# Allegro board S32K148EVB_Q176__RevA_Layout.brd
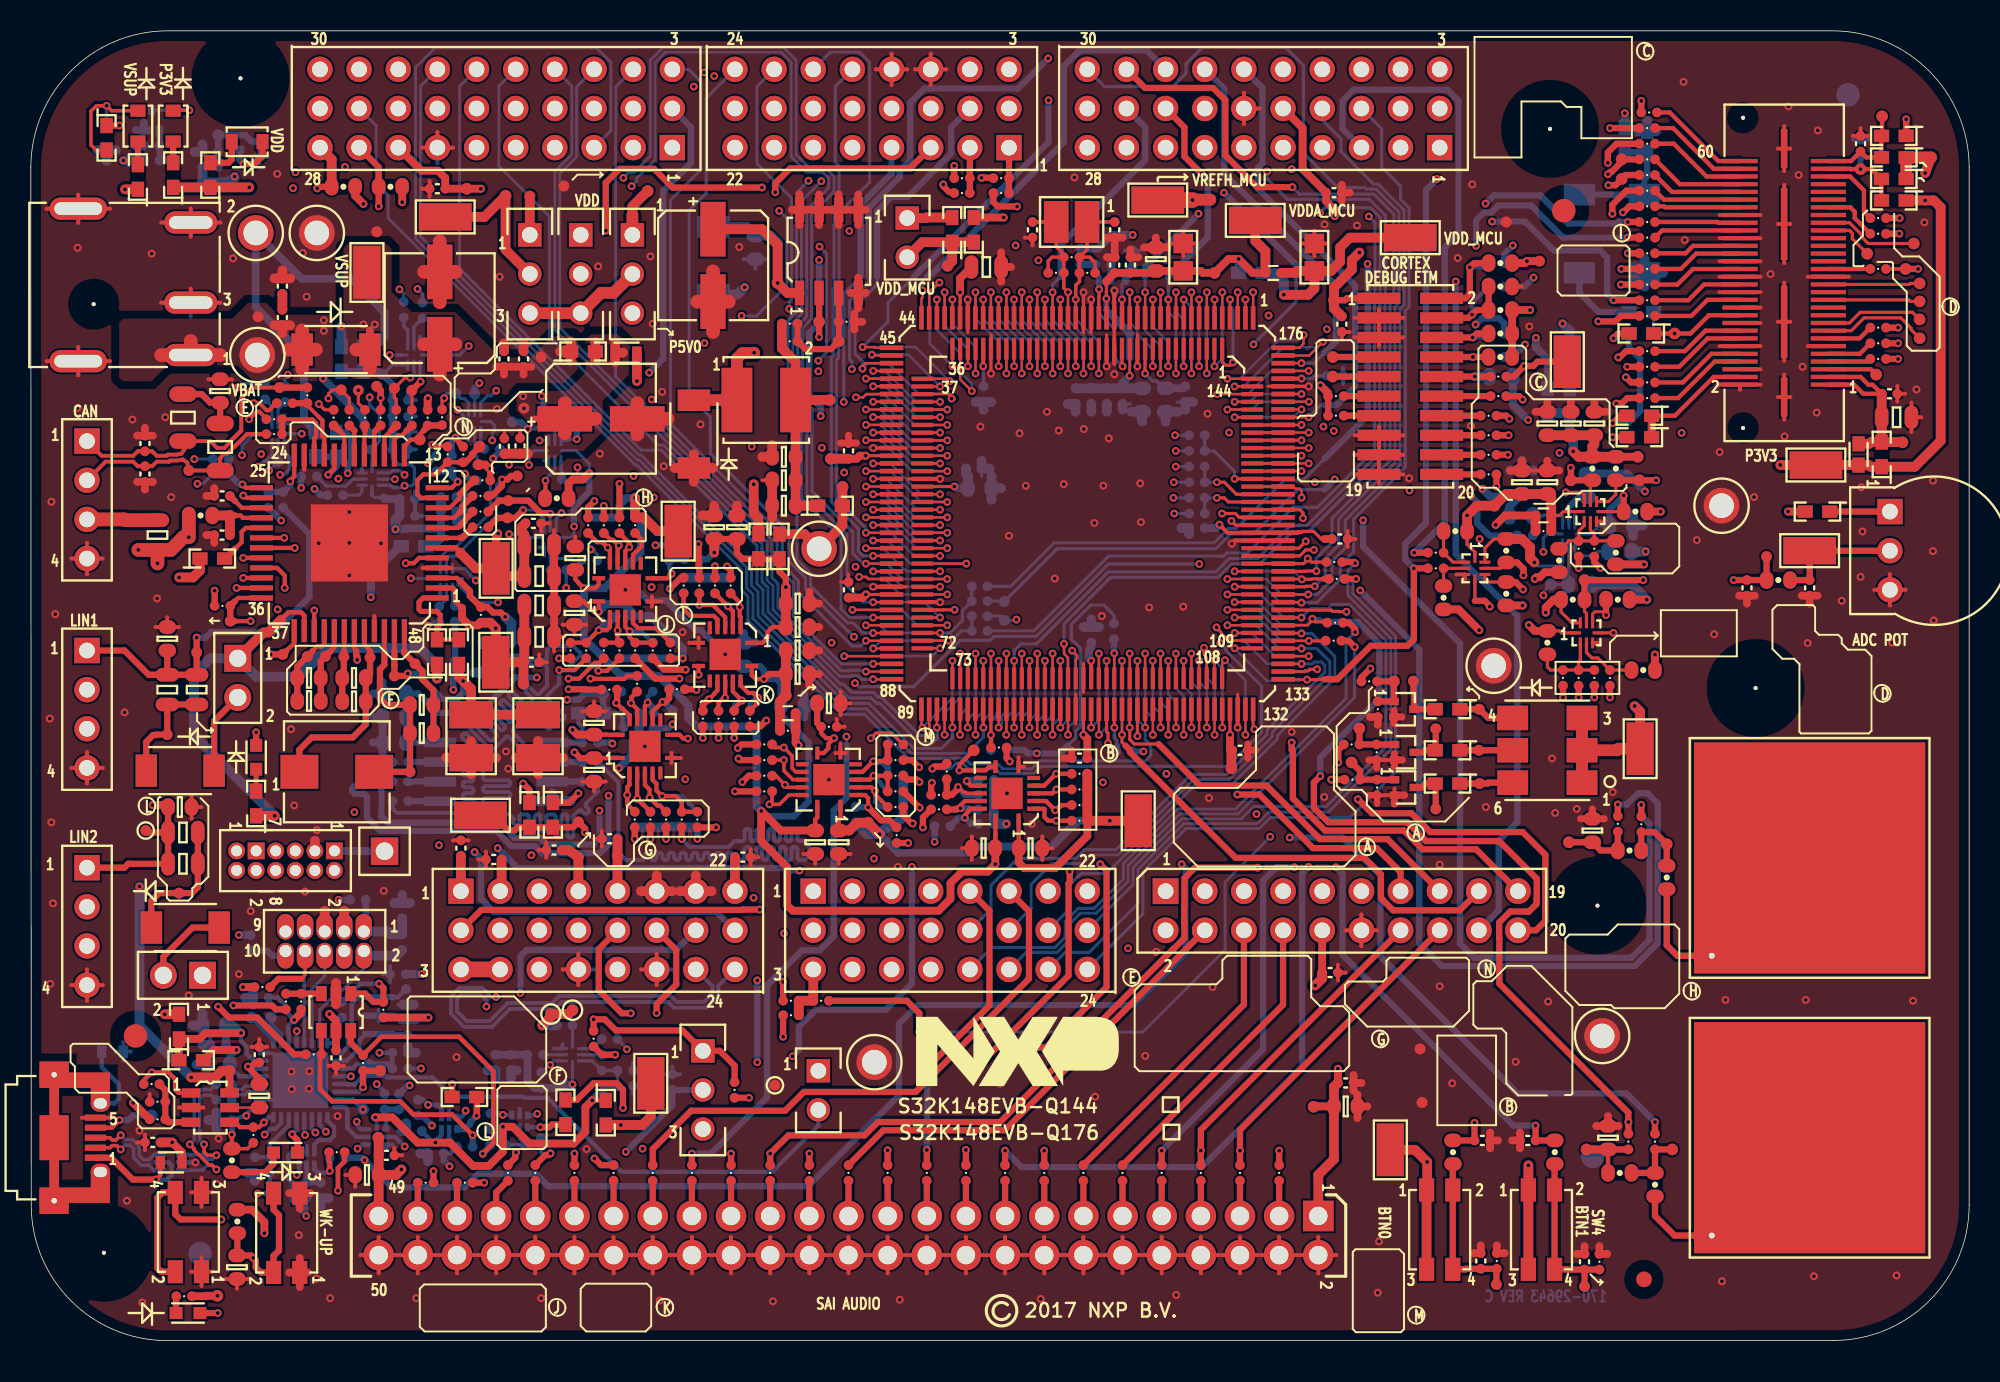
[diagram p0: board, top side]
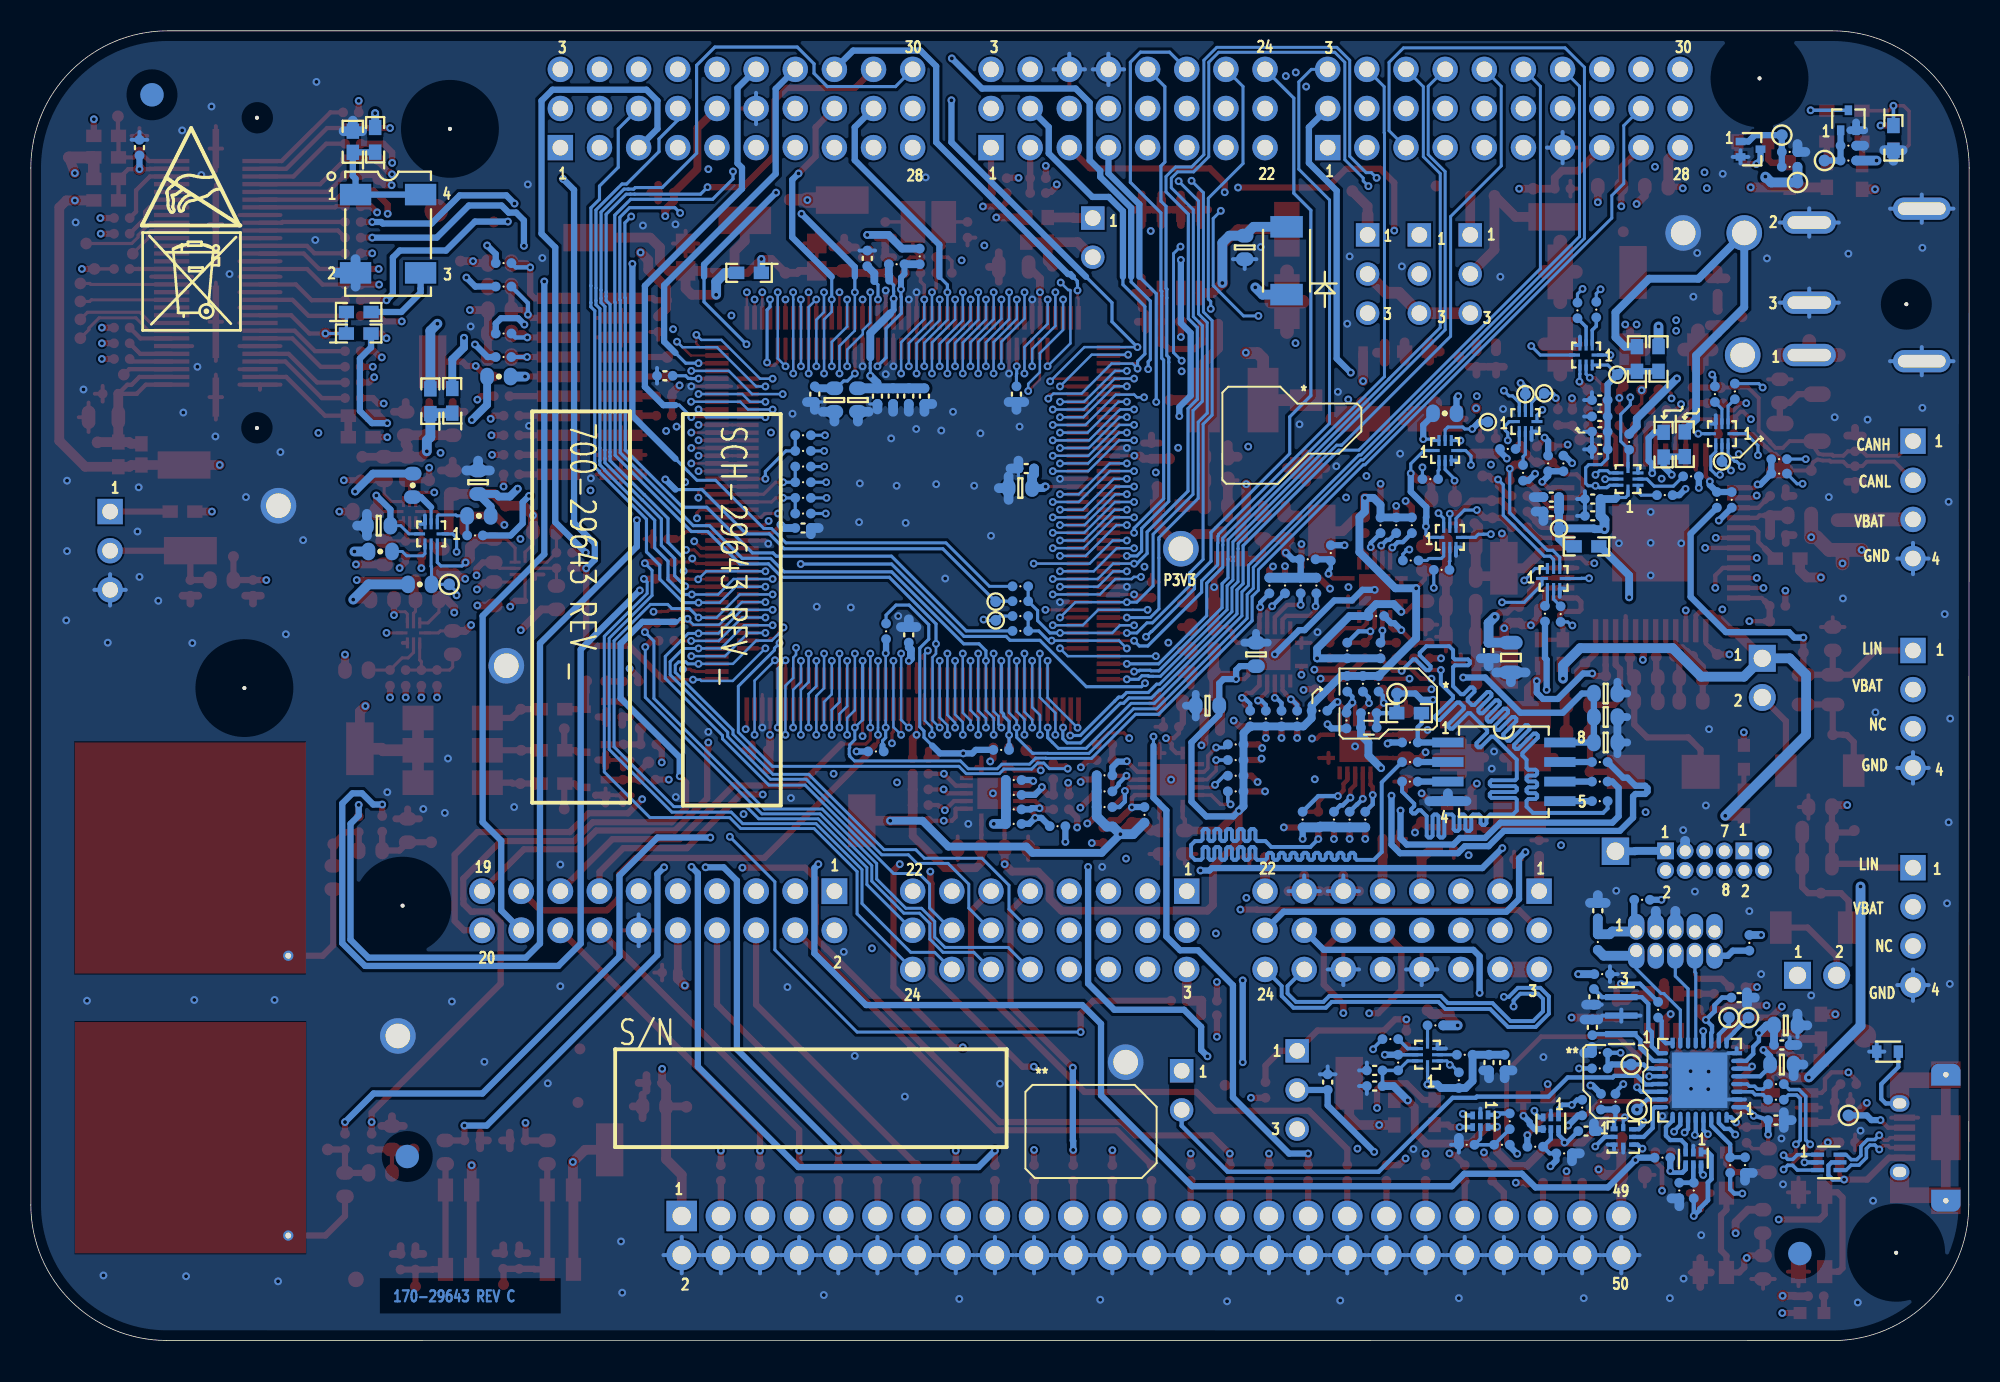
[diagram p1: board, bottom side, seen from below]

Outline 125.76 x 85.01 mm; copper layers: TOP, L2_GND_1, L3_INT_1, L4_PWR_1, L5_PWR_2, L6_INT_2, L7_GND_2, BOTTOM. Coordinates in mm from the lower left corner of the outline.
Outline path: 0,76.12 0.03,8.81 arc(2.6,2.59) 8.83,0 116.94,0.01 arc(123.17,2.59) 125.76,8.81 125.76,76.12 arc(123.15,82.41) 116.87,85.01 8.89,85.01 arc(2.6,82.41) 0,76.12

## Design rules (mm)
net group CLOCK: nets SDA_EXTAL SDA_XTAL
net group DP1: nets N17085305 N17085321
net group DP2: nets CAN_H CAN_L
net group DP3: nets CANH_OUT CANL_OUT
net group DP4: nets SBC_CANH SBC_CANL
net group SDA_USB_CONN_D: nets SDA_USB_CONN_DN SDA_USB_CONN_DP
net group USB_SI_CONN_D: nets SDA_USB_DN SDA_USB_DP
net group MATCH_1: nets ENETSW_INH ENETSW_RESET ENETSW_SCL ENETSW_SDA PTB4/MII_RMII_MDIO PTB5/ENET_MII_RMII_MDC PTB20/FTM6_CH0/ENET_INT PTC0/MII_RMII_RXD1 PTC1/MII_RMII_RXD0 PTC2/MII_RMII_TXD0 PTC17/MII_RMII_RX_DV PTD5/MII_TXD3 PTD6/MII_TXD2 PTD7/MII_RMII_TXD1 PTD8/MII_RXD3 PTD9/MII_RXD2 PTD10/MII_RX_CLK PTD11/MII_RMII_TX_CLK PTD12/MII_RMII_TX_EN
net group MATCH_2: nets PTC2/QSPI_A_IO3 PTC3/QSPI_A_CS PTD7/QSPI_A_IO1 PTD10/QSPI_A_SCK PTD11/QSPI_A_IO0 PTD12/QSPI_A_IO2
net group POW: nets MIC2005_CSLEW POWER_EN SDA_RST SDA_USB_P5V_SENSE VTRG_EN
net group POWER_SPACE: nets P5V0_SDA_USB_CONN_VBUS P5V_SDA_PSW SDA_VOUT33 V_TGTMCU VDD
nets with their own width: min track width 0.254; nets GND

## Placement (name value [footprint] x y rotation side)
C1  0.1uF  [CC0402_25]  26.38 74.76 180 top
C2  0.1uF  [CC0402_25]  84.54 74.51 0 top
C3  12PF  [CC0402_25]  64.99 72.1 270 top
C4  12PF  [CC0402_25]  70.32 72.1 270 top
C5  10uF  [CC0603_OV]  72.99 70.19 90 top
C6  1000pF  [CC0402_25]  70.32 69.81 90 top
C7  1000pF  [CC0402_25]  71.34 69.81 90 top
C8  47uF  [CCE6P8X6P8]  44.26 69.78 270 top
C9  10UF  [CC0805_OV]  61.99 69.68 0 top
C10  0.1uF  [CC0402_25]  16.32 68.44 90 top
C11  47uF  [CCE6P8X6P8]  26.53 67.02 90 top
C12  0.1uF  [CC0402_25]  16.32 66.41 90 top
C13  0.1uF  [CC0402_25]  30.7 63.71 90 top
C14  0.1uF  [CC0402_25]  31.97 63.71 90 top
C15  4700 PF  [CC0603_OV]  12.28 61.63 90 top
C16  47uF  [CCE6P8X6P8]  37 59.83 0 top
C17  1000PF  [CC0603_OV]  98.39 59.52 90 top
C18  0.1UF  [CC0603_OV]  99.91 59.52 90 top
C19  0.1UF  [CC0603_OV]  101.43 59.52 90 top
C20  100PF  [CC0402_25]  7.4 58.23 90 top
C21  0.1uF  [CC0402_25]  31.74 58.07 90 top
C22  0.1uF  [CC0402_25]  30.72 58.05 90 top
C23  1000pF  [CC0402_25]  53.05 57.74 90 top
C24  22uF  [CC0603_OV]  48.86 57.36 180 top
C25  100PF  [CC0402_25]  7.4 56.25 270 top
C26  0.1UF  [CC0603_OV]  48.86 55.84 180 top
C27  0.1UF  [CC0603_OV]  96.74 55.71 90 top
C28  1000PF  [CC0603_OV]  98.39 55.71 90 top
C29  0.01UF  [CC0402_25]  12.41 54.82 180 top
C30  0.1UF  [CC0603_OV]  48.86 54.19 180 top
C31  0.1uF  [CC0402_25]  32.6 53.05 0 top
C32  1000PF  [CC0603_OV]  44.34 52.79 90 top
C41  0.1UF  [CC0603_OV]  45.81 52.79 90 top
C43  0.01UF  [CC0402_25]  12.41 52.28 180 top
C44  1000pF  [CC0402_25]  84.92 52.03 0 top
C45  10UF  [CC0805_OV]  32.98 51.65 0 top
C46  0.1UF  [CC0603_OV]  35.32 50.79 90 top
C47  10UF  [CC0805_OV]  32.98 49.62 0 top
C48  0.1uF  [CC0402_25]  111.34 48.85 270 top
C49  0.1uF  [CC0402_25]  115.4 48.85 270 top
C50  0.1uF  [CC0402_25]  53.05 48.73 90 top
C53  10uF  [CC0603_OV]  49.75 47.84 0 top
C54  10UF  [CC0805_OV]  32.98 47.71 0 top
C55  0.1UF  [CC0603_OV]  35.27 47.23 270 top
C56  0.1UF  [CC0603_OV]  49.75 46.31 0 top
C57  10UF  [CC0805_OV]  32.98 45.68 0 top
C58  220PF  [CC0603_OV]  8.85 45.55 90 top
C59  10uF  [CC0603_OV]  49.75 44.79 0 top
C60  0.1uF  [CC0402_25]  32.47 44.03 0 top
C61  0.1UF  [CC0603_OV]  49.75 43.27 0 top
C62  4700 PF  [CC0603_OV]  18.05 43.01 180 top
C63  4700 PF  [CC0603_OV]  20.97 43.01 180 top
C64  4700 PF  [CC0603_OV]  18.05 41.51 180 top
C65  4700 PF  [CC0603_OV]  20.97 41.49 180 top
C66  10uF  [CC0603_OV]  51.78 41.36 0 top
C67  4700 PF  [CC0603_OV]  25.36 41.26 0 top
C68  0.1UF  [CC0603_OV]  36.54 40.09 90 top
C69  4700 PF  [CC0603_OV]  25.36 39.43 0 top
C70  22uF  [CC1210]  28.56 39.23 270 top
C71  22uF  [CC1210]  32.91 39.23 270 top
C72  0.1uF  [CC0402_25]  78.45 38.31 0 top
C73  1000pF  [CC0402_25]  68.03 37.81 180 top
C75  0.1UF  [CC0603_OV]  36.54 37.04 270 top
C77  220PF  [CC0603_OV]  9.66 34.63 0 top
C78  4.7pF  [CC0603_OV]  101.31 33.11 90 top
C79  0.1uF  [CC0402_25]  37.55 32.57 180 top
C80  0.1UF  [CC0603_OV]  50.89 32.34 270 top
C81  0.1UF  [CC0603_OV]  52.41 32.34 270 top
C82  0.1uF  [CC0402_25]  27.9 31.96 90 top
C83  0.1UF  [CC0603_OV]  61.81 31.96 180 top
C84  0.1UF  [CC0603_OV]  64.86 31.96 0 top
C85  0.1uF  [CC0402_25]  33.95 31.84 180 top
C86  0.1uF  [CC0402_25]  46.19 31.38 0 top
C87  0.1uF  [CC0402_25]  30.04 31.23 180 top
C88  0.1uF  [CC0402_25]  84.29 23.89 0 top
C89  0.1UF  [CC0402_25]  14.82 18.55 90 top
C97  0.1UF  [CC0402_25]  19.8 18.35 270 top
C99  0.1uF  [CC0402_25]  85.31 16.72 0 top
C103  18PF  [CC0603_OV]  14.82 15.89 270 top
C104  10uF  [CC0603_OV]  85.31 15.2 0 top
C108  4.7pF  [CC0603_OV]  102.32 13.17 90 top
C109  0.1uF  [CC0402_25]  94.17 12.99 0 top
C110  0.1uF  [CC0402_25]  97.12 12.99 180 top
C111  10uF  [CC0402_25]  7.91 12.86 180 top
C112  0.1uF  [CC0402_25]  23.08 12.02 0 top
C113  10uF  [CC0603_OV]  21.81 10.75 180 top
C114  0.1uF  [CC0402_25]  94.07 5.17 90 top
C115  0.1uF  [CC0402_25]  100.8 5.12 90 top
C116  4700 PF  [CC0603_OV]  13.37 4.76 270 top
C500  0.1UF  [CC0603]  104.86 77.81 90 bottom
C501  0.1UF  [CC0603_OV]  47 70.95 270 bottom
C502  1000pF  [CC0402_25]  71.49 70.24 90 bottom
C503  0.1uF  [CC0402_25]  84.62 62.62 0 bottom
C504  0.1uF  [CC0402_25]  74.89 61.43 270 bottom
C505  0.1uF  [CC0402_25]  61.81 61.43 270 bottom
C506  0.1uF  [CC0402_25]  70.83 61.3 270 bottom
C507  0.1uF  [CC0402_25]  69.81 61.3 270 bottom
C508  1000pF  [CC0402_25]  68.8 61.3 270 bottom
C509  0.1uF  [CC0402_25]  67.78 61.3 270 bottom
C510  10uF  [CC0603_OV]  73.62 61.05 270 bottom
C511  10uF  [CC0603_OV]  72.1 61.05 270 bottom
C512  0.1uF  [CC0402_25]  23.96 61.05 0 bottom
C513  0.1uF  [CC0402_25]  23.96 59.98 0 bottom
C514  0.1uF  [CC0402_25]  23.96 58.99 0 bottom
C515  0.1uF  [CC0402_25]  23.96 57.85 0 bottom
C516  1000pF  [CC0402_25]  61.18 56.6 0 bottom
C517  0.1UF  [CC0603_OV]  96.74 55.71 90 bottom
C518  10uF  [CC0603_OV]  61.56 55.33 0 bottom
C519  0.1uF  [CC0402_25]  27.11 54.75 0 bottom
C520  0.1uF  [CC0402_25]  24.42 54.62 0 bottom
C521  0.1uF  [CC0402_25]  27.11 53.81 0 bottom
C522  0.1uF  [CC0402_25]  24.42 53.53 0 bottom
C523  0.1UF  [CC0603_OV]  103.19 52.89 0 bottom
C524  1000pF  [CC0402_25]  75.65 52.74 180 bottom
C525  0.1uF  [CC0402_25]  68.8 45.81 90 bottom
C526  0.1uF  [CC0402_25]  31.18 44.79 270 bottom
C527  0.1UF  [CC0603_OV]  46.27 44.54 90 bottom
C528  10UF  [CC0805_OV]  29.73 44.33 270 bottom
C529  1000PF  [CC0603_OV]  23.58 42 180 bottom
C530  1000PF  [CC0603_OV]  49.42 41.21 0 bottom
C531  0.1UF  [CC0603_OV]  23.58 40.47 180 bottom
C532  10uF  [CC0603_OV]  23.58 38.82 180 bottom
C533  0.1UF  [CC0402_25]  24.09 27.9 90 bottom
C534  22PF  [CC0402_25]  24.35 22.31 270 bottom
C535  4.7uF  [CC0402_25]  14.92 22.26 180 bottom
C536  10uF  [CC0603_OV]  11.9 20.46 180 bottom
C537  22PF  [CC0402_25]  24.45 20.33 90 bottom
C538  0.1UF  [CC0402_25]  12.15 19.19 180 bottom
C539  4.7uF  [CC0402_25]  31.15 18.04 270 bottom
C540  0.1UF  [CC0402_25]  30.14 18.04 270 bottom
C541  2.2UF  [CC0603_OV]  12.15 17.92 180 bottom
C542  4.7uF  [CC0402_25]  38.57 17.54 0 bottom
C543  1000pF  [CC0402_25]  41.62 16.77 90 bottom
C544  0.1UF  [CC0402_25]  38.57 16.52 0 bottom
C545  1.0UF  [CC0402_25]  12.53 14.31 180 bottom
C546  4.7uF  [CC0402_25]  24.85 13.6 180 bottom
C547  0.1uF  [CC0402_25]  118.71 77.43 90 bottom
C548  0.1uF  [CC0402_25]  118.71 77.68 90 top
C549  0.1uF  [CC0402_25]  120.59 61.45 0 top
C550  10UF  [CC0805_OV]  121.04 59.93 0 top
C551  0.1uF  [CC0402_25]  85.05 65.97 270 top
D1  VC080505C150RP  [0805]  74.76 70.32 90 top
D2  VC080505C150RP  [0805]  83.27 70.32 90 top
D4  PMEG3050EP  [SOD-128]  19.8 64.32 0 top
D5  PMEG6045ETP  [SOD-128]  43.01 58.84 90 top
D6  LED RED/GRN/BL  [LED6_5X6MM]  98.39 38.31 180 top
D7  LY L29K-H1K2-26-Z  [LED_0603]  14.62 37.86 90 top
D8  PMEG3050EP  [SOD-128]  9.69 36.99 180 top
D9  PMEG3050EP  [SOD-128]  10.02 26.81 180 top
D10  LED GREEN  [LED_0603]  16.52 12.2 0 top
D11  RED  [LED_0603]  10.2 1.79 0 top
D500  PMEG6045ETP  [SOD-128]  44.28 70.09 90 bottom
DS1  ORANGE  [LED2_2P1X1P5_NSP]  6.95 78.83 270 top
DS2  ORANGE  [LED2_2P1X1P5_NSP]  9.23 78.83 270 top
DS3  ORANGE  [LED2_2P1X1P5_NSP]  14.03 77.81 180 top
GND1  5006  [TP_TH_063]  18.55 71.89 0 top
GND2  5006  [TP_TH_063]  109.69 54.19 0 top
GND3  5006  [TP_TH_063]  94.91 43.8 270 top
GND4  5006  [TP_TH_063]  101.94 19.77 0 top
GND5  5006  [TP_TH_063]  54.72 18.07 0 top
J1  ESQ-108-33-T-T  [CON_3X8_100_TH]  63.46 77.43 180 top
J2  ESQ-110-33-T-T  [CON_3X10_100_TH]  41.62 77.43 180 top
J3  ESQ-108-33-T-T  [CON_3X8_100_TH]  27.9 29.17 0 top
J4  ESQ-108-33-T-T  [CON_3X8_100_TH]  50.76 29.17 0 top
J5  CON 2X10  [HDR210_ESQ_SKT]  73.62 29.17 90 top
J6  ESQ-110-33-T-T  [CON_3X10_100_TH]  91.4 77.43 180 top
J7  HDR TH 1X3  [HDR103]  35.67 71.77 0 top
J8  HDR TH 1X3  [HDR103]  39.03 71.77 0 top
J9  CON PWR 3  [CON3_PWR_JACK_TH_PJ051A]  10.38 63.97 0 top
J10  HDR_2X10  [HDR210_FTSH_SM]  89.5 61.94 0 top
J11  HDR 1X4 RA  [CON_HDR_4M_100_TH_RA]  3.64 58.38 270 top
J12  HDR1X2  [HDR1X2_5P48X2P69]  13.42 44.28 270 top
J13  HDR 1X4 RA  [CON_HDR_4M_100_TH_RA]  3.64 44.79 270 top
J14  HDR_2X2  [HDR2X2_50MIL]  14.62 31.79 270 top
J15  HDR_2X4  [HDR2X4_50MIL]  19.7 31.79 270 top
J16  QSH-030-01-L-D-A-K-TR  [CON_60S_QSH_SM_A]  113.75 69.3 90 top
J17  HDR 1X4 RA  [CON_HDR_4M_100_TH_RA]  3.64 30.69 270 top
J18  HDR TH 1X3  [HDR103]  32.37 71.77 0 top
J19  HDR_1X2  [HDR102]  56.86 72.86 0 top
J20  HDR 2X5  [CON_2RH_10_50]  21.6 26.55 180 top
J21  HDR1X2  [HDR1X2_5P48X2P69]  11.14 23.71 180 top
J22  HDR TH 1X3  [HDR103]  43.6 18.81 0 top
J23  HDR 1X2 TH  [SH_HDR102_BOTTOM]  51.09 17.51 0 top
J24  USB_MICRO_AB  [CON_MICROAB_10F_25_SM_RA]  1.61 13.17 0 top
JP1  HDR 1X1  [HDR101_045T]  22.95 31.76 0 top
L1  30 OHM  [IND_0402]  80.61 69.3 180 top
L2  330 OHM  [IND_1608]  38.62 64.12 180 top
L3  4.7uH  [IND_5P2X5P2]  47.71 61.05 0 top
L4  120OHM  [IND_0603]  118.58 57.52 90 top
L6  30 OHM  [IND_0402]  98.13 53.55 0 top
L7  30 OHM  [IND_0402]  49.11 40.73 180 top
L8  22uH  [IND2_6P5X6P2MM_SM]  19.85 36.92 0 top
L9  330 OHM  [IND_1608]  9.11 11.57 0 top
L500  30 OHM  [IND_0402]  38.95 39.79 0 bottom
L501  330 OHM  [IND_1608]  5.3 18.76 0 bottom
NOREF  -  []  28.79 59 0 top
NOREF#2  -  []  50.76 24.09 0 top
NOREF#3  -  []  41.56 37.82 90 top
NOREF#4  -  []  17.56 45.75 90 top
NOREF#5  -  []  8.89 85.01 0 top
NOREF#6  -  []  26.25 22.82 0 top
NOREF#7  -  []  45.68 26.63 90 top
NOREF#8  -  []  11.07 4.47 90 top
NOREF#9  -  []  2.13 81.89 0 top
NOREF#10  -  []  7.49 36.99 0 top
NOREF#11  -  []  24.45 64.62 0 top
NOREF#12  -  [unnamed#2]  99.45 73.34 0 top
NOREF#13  -  []  26.2 34.16 0 top
NOREF#14  -  []  34.49 18.15 90 top
NOREF#15  -  []  68.54 82.51 0 top
NOREF#16  -  []  34.42 51.51 0 top
NOREF#17  -  []  33.29 51.48 90 top
NOREF#18  -  []  62.83 16.01 0 top
NOREF#19  -  []  64.41 35.19 0 top
NOREF#20  -  []  96.49 43.8 0 top
NOREF#21  -  []  56.31 18.07 0 top
NOREF#22  -  []  39.57 47 90 top
NOREF#23  -  []  125.76 8.81 90 top
NOREF#24  -  []  65.11 83.78 0 top
NOREF#25  -  [unnamed#2]  101.64 28.23 0 top
NOREF#26  -  []  93.69 49.37 90 top
NOREF#27  -  []  42.93 70.79 0 top
NOREF#28  -  []  52.73 51.39 0 top
NOREF#29  -  []  93.04 50.12 90 top
NOREF#30  -  [unnamed#2]  4.74 5.7 0 top
NOREF#31  -  []  26.96 48.81 0 top
NOREF#32  -  []  104.61 4.8 90 top
NOREF#33  -  []  101.38 53.19 90 top
NOREF#34  -  []  103.21 25.36 90 top
NOREF#35  -  []  0 76.12 0 top
NOREF#36  -  []  61.61 36.52 0 top
NOREF#37  -  []  105.5 4.38 0 top
NOREF#38  -  []  18.09 25.05 90 top
NOREF#39  -  []  103.53 19.77 0 top
NOREF#40  -  [unnamed#2]  111.9 42.35 0 top
NOREF#41  -  []  100.53 45.28 0 top
NOREF#42  -  []  36.84 47.98 0 top
NOREF#43  -  []  42.93 68.09 90 top
NOREF#44  -  []  15.64 59.51 0 top
NOREF#45  -  []  98.13 25.36 0 top
NOREF#46  -  []  21.49 33.12 0 top
NOREF#47  -  []  59.79 42.98 90 top
NOREF#48  -  []  116.94 0.01 90 top
NOREF#49  -  []  24.41 30.4 90 top
NOREF#50  -  []  50.31 58.45 90 top
NOREF#51  -  []  12.02 28.16 90 top
NOREF#52  -  []  100.2 45.31 0 top
NOREF#53  -  []  28.99 59.03 90 top
NOREF#54  -  []  130.47 -13.91 0 top
NOREF#55  -  []  34.2 57.15 90 top
NOREF#56  -  []  17.8 62.97 90 top
NOREF#57  -  []  19.85 0 90 top
NOREF#58  -  []  88.86 82.51 0 top
NOREF#59  -  []  34 57.12 0 top
NOREF#60  -  []  26.56 35.01 90 top
NOREF#61  -  []  26.56 35.01 0 top
NOREF#62  -  []  51.49 34.39 0 top
NOREF#63  -  []  93.06 50.85 0 top
NOREF#64  -  []  70.19 22.82 90 top
NOREF#65  -  []  7.82 26.81 0 top
NOREF#66  -  []  -98.69 -309.48 0 top
NOREF#67  -  []  52.85 36.08 0 top
NOREF#68  -  []  84 69.21 0 top
NOREF#69  -  []  37.57 47 0 top
NOREF#70  -  []  12.02 30.86 0 top
NOREF#71  -  []  38.84 36.84 0 top
NOREF#72  -  []  73.62 29.17 0 top
NOREF#73  -  [unnamed#2]  6.79 19.77 0 top
NOREF#74  -  []  69.43 83.78 90 top
NOREF#75  -  []  40.39 46.9 90 top
NOREF#76  -  []  100.11 -20.92 0 top
NOREF#77  -  []  65.06 34.52 90 top
NOREF#78  -  []  8.42 13.05 0 top
NOREF#79  -  []  198.26 -169.31 0 top
NOREF#80  -  []  22.57 5.55 0 top
NOREF#81  -  []  33.69 51.48 0 top
NOREF#82  -  []  16.79 58.86 90 top
NOREF#83  -  []  135.92 59.61 0 top
NOREF#84  -  []  26.2 34.16 0 top
NOREF#85  -  []  90.55 9.77 0 top
NOREF#86  -  []  12.08 45.75 0 top
NOREF#87  -  []  17.8 65.67 0 top
NOREF#88  -  [unnamed#2]  104.66 3.97 0 top
NOREF#89  -  []  68.54 26.63 90 top
NOREF#90  -  []  16.18 71.89 0 top
NOREF#91  -  []  35.34 17.93 90 top
NOREF#92  -  []  26.56 35.01 90 top
NOREF#93  -  []  111.28 54.19 0 top
NOREF#94  -  []  75.49 69.21 0 top
NOREF#95  -  []  100.46 53.18 0 top
NOREF#96  -  []  99.38 53.01 0 top
NOREF#97  -  []  43.27 83.78 0 top
NOREF#98  -  []  33.6 57.12 90 top
NOREF#99  -  []  6.95 77.83 90 top
NOREF#100  -  []  44.36 59.54 0 top
NOREF#101  -  []  68.06 34.44 90 top
NOREF#102  -  []  9.37 4.47 0 top
NOREF#103  -  []  78.85 67.87 0 top
NOREF#104  -  []  34.72 57.14 0 top
NOREF#105  -  []  21.49 56.32 90 top
NOREF#106  -  []  11.69 38.34 90 top
NOREF#107  -  []  22.34 55.3 90 top
NOREF#108  -  []  93.89 49.5 90 top
NOREF#109  -  []  101.58 53.16 90 top
NOREF#110  -  []  106.04 41.36 90 top
NOREF#111  -  []  45.81 61.05 0 top
NOREF#112  -  []  24.19 27.37 90 top
NOREF#113  -  []  31.65 34.17 90 top
NOREF#114  -  []  33.89 51.51 90 top
NOREF#115  -  []  53.34 65.6 0 top
NOREF#116  -  []  43.01 56.64 90 top
NOREF#117  -  []  25.05 63.35 90 top
NOREF#118  -  []  97.16 4.62 90 top
NOREF#119  -  [unnamed#2]  98.56 78.65 0 top
NOREF#120  -  []  40.29 47.98 90 top
NOREF#121  -  []  101.13 45.31 90 top
NOREF#122  -  []  96.14 36.21 90 top
NOREF#123  -  []  50.05 37.41 0 top
NOREF#124  -  []  73.62 29.17 0 top
NOREF#125  -  []  8.66 -38.53 0 top
NOREF#126  -  []  51.03 38.13 0 top
NOREF#127  -  []  13.03 77.81 0 top
NOREF#128  -  []  0.02 12.13 0 top
NOREF#129  -  []  68.54 77.43 90 top
NOREF#130  -  []  45.11 58.45 0 top
NOREF#131  -  []  97.16 9.77 0 top
NOREF#132  -  []  86.21 69.21 90 top
NOREF#133  -  []  45.37 47.11 0 top
NOREF#134  -  []  99.98 51.74 90 top
NOREF#135  -  []  16.24 58.24 90 top
NOREF#136  -  []  95.76 63.06 270 top
NOREF#137  -  []  17.6 64.32 0 top
NOREF#138  -  []  8.6 23.71 0 top
NOREF#139  -  []  -408 -310.75 0 top
NOREF#140  -  []  44.28 67.89 90 top
NOREF#141  -  []  38.11 37.82 0 top
NOREF#142  -  []  18.76 82.51 0 top
NOREF#143  -  []  93.2 8.4 0 top
NOREF#144  -  []  15.51 29.91 0 top
NOREF#145  -  []  99.81 8.4 0 top
NOREF#146  -  []  -30.62 -120.06 0 top
NOREF#147  -  []  17.45 4.42 90 top
NOREF#148  -  []  45.55 46.26 0 top
NOREF#149  -  []  43.32 45.29 0 top
NOREF#150  -  []  52.53 34.68 90 top
NOREF#151  -  []  28.39 59 90 top
NOREF#152  -  []  86.19 83.78 90 top
NOREF#153  -  []  31.65 34.17 90 top
NOREF#154  -  []  27.16 48.84 90 top
NOREF#155  -  []  64.08 33.79 90 top
NOREF#156  -  []  45.68 77.43 90 top
NOREF#157  -  []  130.77 36.28 0 top
NOREF#158  -  []  13.35 31.79 0 top
NOREF#159  -  []  44.36 56.84 90 top
NOREF#160  -  []  119.21 83.78 90 top
NOREF#161  -  []  14.8 13 0 top
NOREF#162  -  []  26.56 35.01 0 top
NOREF#163  -  []  57.84 57.93 90 top
NOREF#164  -  []  18.76 77.43 90 top
NOREF#165  -  []  21.49 55.52 90 top
NOREF#166  -  []  49.02 46.36 90 top
NOREF#167  -  []  58.54 63.68 0 top
NOREF#168  -  []  15.75 4.42 0 top
NOREF#169  -  []  20.59 27.37 0 top
NOREF#170  -  []  99.06 52.98 0 top
NOREF#171  -  []  78.54 63.68 90 top
NOREF#172  -  []  38.01 37.49 0 top
NOREF#173  -  []  -381.97 214.4 0 top
NOREF#174  -  []  25.6 63.97 90 top
NOREF#175  -  []  13.22 9.45 90 top
NOREF#176  -  []  101.33 45.28 90 top
NOREF#177  -  []  57.84 62.43 0 top
NOREF#178  -  []  11.69 41.04 0 top
NOREF#179  -  []  62.58 37.24 0 top
NOREF#180  -  []  40.84 36.84 90 top
NOREF#181  -  []  13.42 41.74 90 top
NOREF#182  -  []  27.9 24.09 0 top
NOREF#183  -  []  39.08 82.51 0 top
NOREF#184  -  []  20.14 71.89 0 top
NOREF#185  -  []  77.7 69.21 90 top
NOREF#186  -  []  27.9 24.09 0 top
NOREF#187  -  []  16.28 63.97 0 top
NOREF#188  -  []  24.13 64.59 0 top
NOREF#189  -  []  83.27 69.43 90 top
NOREF#190  -  []  100.78 53.16 0 top
NOREF#191  -  []  47.33 22.82 90 top
NOREF#192  -  []  93.05 83.78 0 top
NOREF#193  -  []  60.59 1.94 0 top
NOREF#194  -  []  29.52 59.02 0 top
NOREF#195  -  []  180.28 85.26 0 top
NOREF#196  -  []  60.92 82.51 0 top
NOREF#197  -  []  45.68 82.51 0 top
NOREF#198  -  []  56.5 35.33 90 top
NOREF#199  -  []  18.43 31.79 0 top
NOREF#200  -  []  34.49 18.95 90 top
NOREF#201  -  []  26.56 35.01 90 top
NOREF#202  -  []  53.5 35.41 90 top
NOREF#203  -  []  26.56 35.01 90 top
NOREF#204  -  []  27.69 48.84 0 top
NOREF#205  -  []  15.32 59.49 0 top
NOREF#206  -  []  74.76 69.43 90 top
NOREF#207  -  []  96.14 40.41 0 top
NOREF#208  -  []  34.52 17.83 0 top
NOREF#209  -  []  26.56 48.81 90 top
NOREF#210  -  [unnamed#2]  13.6 81.93 0 top
NOREF#211  -  []  36.74 47.65 0 top
NOREF#212  -  []  12.61 25.05 0 top
NOREF#213  -  []  50.76 24.09 0 top
NOREF#214  -  []  19.6 9.4 90 top
NOREF#215  -  []  43.32 43.79 90 top
NOREF#216  -  []  21.51 55.19 0 top
NOREF#217  -  []  100.94 41.36 0 top
NOREF#218  -  []  49.11 22.82 0 top
NOREF#219  -  []  44.05 42.81 90 top
NOREF#220  -  []  41.66 36.74 90 top
NOREF#221  -  []  19.11 29.91 90 top
NOREF#222  -  []  9.23 77.83 90 top
NOREF#223  -  []  96.48 26.63 90 top
NOREF#224  -  []  90.55 4.62 90 top
NOREF#225  -  []  98 4.8 90 top
NOREF#226  -  []  100.53 52.36 90 top
NOREF#227  -  []  91.82 68.65 180 bottom
NOREF#228  -  []  154.27 61.05 270 bottom
NOREF#229  -  []  150.33 76.79 180 bottom
NOREF#230  -  []  54.61 34.64 180 bottom
NOREF#231  -  []  165.32 74.38 270 bottom
NOREF#232  -  [unnamed#2]  10.99 5.65 180 bottom
NOREF#233  -  [unnamed#2]  117.89 80.86 180 bottom
NOREF#234  -  []  153.89 64.35 180 bottom
NOREF#235  -  []  54.66 42.01 180 bottom
NOREF#236  -  [unnamed#2]  101.33 11.95 180 bottom
NOREF#237  -  []  121.45 63.79 180 bottom
NOREF#238  -  []  177.63 32.34 180 bottom
P1  TSW-125-07-F-D  [HDR225]  83.53 8.09 270 top
Q1  MMBT3904TT1G  [SC_75]  89.09 40.98 270 top
Q2  MMBT3904TT1G  [SC_75]  89.12 38.19 270 top
Q3  MMBT3904TT1G  [SC_75]  89.12 35.9 270 top
Q500  MMBT3904TT1G  [SC_75]  7.84 79.21 180 bottom
Q501  MMBT3904TT1G  [SC_75]  14.19 77.33 270 bottom
R1  33 OHM  [RC0402_25]  104.99 79.72 180 top
R2  33  [RC0402_25]  104.86 78.7 180 top
R3  0  [RC0603]  120.87 78.19 180 top
R4  0  [RC0603]  4.91 78.06 270 top
R5  33 OHM  [RC0402_25]  104.86 77.68 180 top
R6  0  [RC0603]  120.87 76.79 180 top
R7  33 OHM  [RC0402_25]  104.86 76.67 180 top
R8  33 OHM  [RC0402_25]  104.86 75.65 180 top
R9  560  [RC0603]  9.23 75.65 90 top
R12  560  [RC0603]  11.65 75.65 90 top
R13  1.8K  [RC0603]  6.95 75.52 90 top
R14  0  [RC0402_25]  60.41 75.45 0 top
R34  0  [RC0402_25]  62.95 75.45 0 top
R35  0  [RC0603]  120.87 75.4 180 top
R36  10K  [RC0603_OV]  20.28 74.89 180 top
R37  10K  [RC0603_OV]  23.33 74.89 180 top
R38  33 OHM  [RC0402_25]  104.86 74.64 180 top
R39  0  [RC0402_25]  60.41 74.48 0 top
R40  0  [RC0402_25]  62.95 74.48 0 top
R41  0  [RC0603]  120.87 74 180 top
R46  33 OHM  [RC0402_25]  104.86 73.62 180 top
R55  0  [RC0402_25]  119.85 72.86 180 top
R58  33 OHM  [RC0402_25]  104.86 72.6 180 top
R59  0  [RC0603]  59.78 72.1 90 top
R60  0  [RC0603]  61.18 72.1 90 top
R61  0  [RC0402_25]  119.85 71.84 180 top
R62  33 OHM  [RC0402_25]  104.86 71.59 180 top
R63  33 OHM  [RC0402_25]  104.86 70.57 180 top
R64  0  [RC0402_25]  67.53 70.32 180 top
R72  10K  [RC0603_OV]  95.34 69.94 180 top
R74  33 OHM  [RC0402_25]  104.86 69.56 180 top
R75  0  [RC0402_25]  119.85 69.56 180 top
R76  0  [RC0402_25]  66.51 69.3 0 top
R78  0  [RC0402_25]  68.54 69.3 180 top
R79  33 OHM  [RC0402_25]  104.86 68.54 180 top
R80  10K  [RC0603_OV]  95.34 68.41 0 top
R81  33 OHM  [RC0402_25]  104.86 67.52 180 top
R90  10K  [RC0603_OV]  95.34 66.89 180 top
R91  33 OHM  [RC0402_25]  104.86 66.51 180 top
R92  1.0K  [RC0402_25]  52.92 66.13 0 top
R93  3.09K  [RC0402_25]  49.24 66 0 top
R94  0  [RC0402_25]  119.85 65.75 180 top
R95  10K  [RC0603_OV]  95.34 65.36 180 top
R96  0  [RC0603]  104.48 65.36 180 top
R97  1.69K  [RC0402_25]  49.24 64.86 0 top
R98  0  [RC0402_25]  119.85 64.73 180 top
R102  33 OHM  [RC0402_25]  104.86 64.22 180 top
R106  0  [RC0603]  35.83 64.2 0 top
R107  10K  [RC0603_OV]  95.34 63.84 180 top
R108  0  [RC0402_25]  119.85 63.71 180 top
R109  33 OHM  [RC0402_25]  104.86 63.21 180 top
R110  0  [RC0402_25]  95.21 62.57 0 top
R111  33 OHM  [RC0402_25]  104.86 62.19 180 top
R112  0  [RC0402_25]  17.95 61.35 90 top
R113  0  [RC0402_25]  84.67 61.3 0 top
R114  0  [RC0402_25]  95.21 61.3 0 top
R115  33 OHM  [RC0402_25]  104.86 61.17 180 top
R119  0  [RC0402_25]  16.47 60.84 180 top
R121  0  [RC0402_25]  84.67 60.03 0 top
R122  0  [RC0402_25]  94.58 60.03 0 top
R123  0  [RC0603]  104.36 60.03 180 top
R124  0  [RC0402_25]  26.68 59.93 90 top
R125  60.4  [RC1206_OV]  9.87 59.9 90 top
R126  0  [RC0402_25]  19.65 59.9 270 top
R127  0  [RC0402_25]  20.66 59.9 270 top
R128  0  [RC0402_25]  21.68 59.9 270 top
R129  0  [RC0402_25]  22.69 59.9 270 top
R130  0  [RC0402_25]  23.71 59.9 270 top
R131  0  [RC0402_25]  24.73 59.9 270 top
R132  10.0K  [RC0402_25]  25.74 59.9 270 top
R133  0  [RC0603]  120.08 57.52 90 top
R134  0  [RC0402_25]  15.79 59.8 180 top
R135  0  [RC0402_25]  15.79 58.84 180 top
R136  0  [RC0402_25]  94.58 58.76 0 top
R137  0  [RC0603]  104.36 58.63 180 top
R138  60.4  [RC1206_OV]  12.28 58 270 top
R139  0  [RC0402_25]  27.04 57.52 90 top
R140  10.0K  [RC0402_25]  28.05 57.52 270 top
R141  0  [RC0402_25]  94.58 57.49 0 top
R142  10K  [RC0603_OV]  101.31 56.6 270 top
R144  10K  [RC0603_OV]  102.83 56.6 270 top
R148  0  [RC0402_25]  94.58 56.22 0 top
R149  0  [RC0402_25]  29.3 55.84 180 top
R150  0  [RC0402_25]  29.17 54.82 180 top
R153  10K  [RC0603_OV]  34.12 54.67 180 top
R154  0  [RC0402_25]  29.17 53.81 180 top
R156  10K  [RC0603_OV]  104.1 53.81 180 top
R161  0  [RC0603]  115.91 53.81 180 top
R163  1.0K  [RC0603_OV]  11.01 53.55 0 top
R165  0  [RC0402_25]  36.16 52.92 270 top
R173  0  [RC0402_25]  37.17 52.92 270 top
R175  0  [RC0402_25]  38.19 52.92 270 top
R176  51K  [RC0402_25]  39.2 52.92 270 top
R177  0  [RC0402_25]  29.17 52.79 180 top
R178  10K  [RC0603_OV]  92.42 52.54 180 top
R179  0  [RC0402_25]  98.13 52.54 0 top
R180  0  [RC0805_OV]  8.22 52.28 270 top
R181  0  [RC0603]  47.21 51.55 90 top
R182  0  [RC0603]  48.58 51.55 90 top
R183  0  [RC0402_25]  100.42 51.39 90 top
R184  0  [RC0402_25]  101.43 51.39 90 top
R185  10K  [RC0603_OV]  95.72 51.27 270 top
R186  5K  [POT3_3352T]  120.61 53.81 270 top
R187  0  [RC0402_25]  91.15 51.14 0 top
R188  10K  [RC0603_OV]  102.83 51.14 90 top
R189  0  [RC0603]  11.77 50.76 0 top
R190  10K  [RC0603_OV]  99.15 50.63 90 top
R191  0  [RC0402_25]  84.57 50.53 180 top
R192  0  [RC0402_25]  91.15 50.12 0 top
R193  0  [RC0402_25]  84.72 49.44 180 top
R194  220  [RC0603_OV]  113.37 49.36 180 top
R195  0  [RC0402_25]  42.35 49.01 90 top
R196  0  [RC0402_25]  43.37 49.01 90 top
R197  0  [RC0402_25]  44.39 49.01 90 top
R198  0  [RC0402_25]  45.4 49.01 90 top
R199  10K  [RC0603_OV]  95.72 48.47 90 top
R200  10K  [RC0603_OV]  91.66 48.22 90 top
R201  10K  [RC0603_OV]  100.04 48.09 0 top
R202  10K  [RC0603_OV]  102.96 48.09 180 top
R203  0  [RC0402_25]  12.43 47.69 0 top
R204  0  [RC0402_25]  29.2 47.1 270 top
R205  0  [RC0402_25]  84.62 46.59 180 top
R206  0  [RC0402_25]  84.52 45.43 180 top
R207  10K  [RC0603_OV]  98.39 45.3 270 top
R208  0  [RC0402_25]  35.01 44.79 270 top
R209  0  [RC0402_25]  36.03 44.79 270 top
R210  0  [RC0402_25]  37.17 44.79 270 top
R211  0  [RC0402_25]  38.19 44.79 270 top
R212  0  [RC0402_25]  39.2 44.79 270 top
R213  0  [RC0402_25]  40.35 44.79 270 top
R214  51K  [RC0402_25]  41.49 44.79 90 top
R215  0  [RC0603]  26.35 44.69 90 top
R216  0  [RC0603]  27.77 44.69 90 top
R217  10K  [RC0603_OV]  104.61 43.52 180 top
R218  0  [RC0402_25]  99.4 43.01 90 top
R219  0  [RC0402_25]  100.42 43.01 90 top
R220  0  [RC0402_25]  101.43 43.01 90 top
R221  0  [RC0402_25]  102.45 43.01 90 top
R222  10.0K  [RC0402_25]  86.83 42.78 180 top
R223  0  [RC0402_25]  39.33 42.63 270 top
R224  0  [RC0402_25]  41.92 42.28 180 top
R225  2K  [RC0805_OV]  8.85 42.25 270 top
R226  2K  [RC0805_OV]  10.76 42.25 270 top
R227  0  [RC0402_25]  37.53 42.25 0 top
R228  33K  [RC0402_25]  87.39 40.98 270 top
R229  560  [RC0603]  91.91 40.98 180 top
R230  0  [RC0402_25]  43.6 40.37 90 top
R231  0  [RC0402_25]  44.62 40.37 90 top
R232  0  [RC0402_25]  45.63 40.37 90 top
R233  0  [RC0402_25]  46.65 40.37 90 top
R234  51K  [RC0402_25]  51.78 39.84 0 top
R242  0  [RC0402_25]  49.11 39.58 180 top
R243  0  [RC0402_25]  47.59 38.69 0 top
R244  0  [RC0402_25]  56.1 38.69 0 top
R245  10.0K  [RC0402_25]  85.69 38.69 180 top
R246  0  [RC0402_25]  62.8 38.49 180 top
R247  560  [RC0603]  91.91 38.31 180 top
R248  33K  [RC0402_25]  87.31 38.19 270 top
R249  0  [RC0402_25]  47.59 37.68 0 top
R250  0  [RC0402_25]  56.1 37.68 0 top
R251  0  [RC0402_25]  59.42 36.94 270 top
R252  51K  [RC0402_25]  68.03 36.79 180 top
R253  0  [RC0402_25]  47.59 36.66 0 top
R254  0  [RC0402_25]  56.1 36.66 0 top
R255  10.0K  [RC0402_25]  85.74 36.41 180 top
R256  560  [RC0603]  91.91 36.15 180 top
R257  33K  [RC0402_25]  87.34 35.9 270 top
R258  51K  [RC0402_25]  68.03 35.77 180 top
R259  0  [RC0402_25]  47.59 35.65 0 top
R260  0  [RC0402_25]  56.1 35.65 0 top
R261  0  [RC0402_25]  58.92 35.42 0 top
R262  1.8K  [RC0603]  14.62 34.86 90 top
R263  51K  [RC0402_25]  68.03 34.76 180 top
R264  0  [RC0402_25]  56.1 34.63 0 top
R265  0  [RC0402_25]  58.92 34.48 0 top
R266  0  [RC0603]  32.35 34.12 270 top
R267  0  [RC0603]  33.87 34.12 270 top
R268  0  [RC0402_25]  39.18 33.82 270 top
R269  0  [RC0402_25]  40.2 33.82 270 top
R270  0  [RC0402_25]  41.21 33.82 270 top
R271  0  [RC0402_25]  42.23 33.82 270 top
R272  0  [RC0402_25]  43.24 33.82 270 top
R273  51K  [RC0402_25]  68.03 33.74 180 top
R274  0  [RC0402_25]  102.96 33.54 90 top
R275  0  [RC0402_25]  104.48 33.51 90 top
R276  2K  [RC0805_OV]  9.87 32.98 0 top
R277  0  [RC0402_25]  56.17 32.8 270 top
R278  4.7K  [RC0603_OV]  103.72 31.81 0 top
R279  2K  [RC0805_OV]  9.87 30.95 0 top
R280  0  [RC0603_OV]  106.13 30.06 270 top
R281  10.0K  [RC0402_25]  15.02 22.95 0 top
R282  0  [RC0402_25]  49.31 22.06 0 top
R283  0  [RC0402_25]  51.27 22.06 180 top
R284  0  [RC0402_25]  16.55 22.01 270 top
R285  10.0K  [RC0402_25]  17.54 22.01 270 top
R286  10.0K  [RC0402_25]  22.87 21.47 90 top
R287  0  [RC0402_25]  49.31 21.12 0 top
R288  0  [RC0603]  9.61 20.38 90 top
R289  0  [RC0402_25]  36.51 19.59 90 top
R290  0  [RC0402_25]  18.35 18.58 180 top
R291  0  [RC0603]  10.4 18.2 0 top
R292  0  [RC0402_25]  21.55 18.02 270 top
R293  10.0K  [RC0402_25]  7.84 16.65 0 top
R294  0  [RC0603]  28.13 15.81 180 top
R295  0  [RC0402_25]  45.66 16.27 90 top
R296  15K  [RC0402_25]  8.22 15.5 180 top
R298  0  [RC0603]  34.68 14.82 90 top
R299  0  [RC0603]  37.3 14.79 270 top
R300  1.0K  [RC0402_25]  8.22 14.36 0 top
R301  10.0K  [RC0402_25]  14.44 13.35 90 top
R302  0  [RC0402_25]  103.64 12.91 90 top
R304  0  [RC0402_25]  105.37 12.91 90 top
R305  0  [RC0402_25]  19.85 12.23 0 top
R306  220  [RC0603_OV]  92.27 12.23 90 top
R307  220  [RC0603_OV]  98.87 12.23 90 top
R308  220  [RC0603_OV]  13.04 11.69 270 top
R309  33 OHM  [RC0402_25]  30.95 10.88 270 top
R310  33 OHM  [RC0402_25]  32.73 10.88 270 top
R311  33 OHM  [RC0402_25]  35.27 10.88 270 top
R312  33 OHM  [RC0402_25]  37.81 10.88 270 top
R313  33 OHM  [RC0402_25]  40.35 10.88 270 top
R314  33 OHM  [RC0402_25]  42.89 10.88 270 top
R315  33 OHM  [RC0402_25]  45.43 10.88 270 top
R316  33 OHM  [RC0402_25]  47.97 10.88 270 top
R317  33 OHM  [RC0402_25]  50.51 10.88 270 top
R318  33 OHM  [RC0402_25]  53.05 10.88 270 top
R319  33 OHM  [RC0402_25]  55.59 10.88 270 top
R320  33 OHM  [RC0402_25]  58.13 10.88 270 top
R321  33 OHM  [RC0402_25]  60.67 10.88 270 top
R322  33 OHM  [RC0402_25]  63.21 10.88 270 top
R323  33 OHM  [RC0402_25]  65.75 10.88 270 top
R324  33 OHM  [RC0402_25]  68.29 10.88 270 top
R325  33 OHM  [RC0402_25]  70.83 10.88 270 top
R326  33 OHM  [RC0402_25]  73.37 10.88 270 top
R327  33 OHM  [RC0402_25]  75.91 10.88 270 top
R328  33 OHM  [RC0402_25]  78.45 10.88 270 top
R329  33 OHM  [RC0402_25]  80.99 10.88 270 top
R330  4.7K  [RC0603_OV]  103.09 10.88 0 top
R331  33 OHM  [RC0402_25]  25.62 10.25 180 top
R332  33 OHM  [RC0402_25]  28.16 10.25 180 top
R333  0  [RC0603_OV]  105.37 10.12 270 top
R334  10K  [RC0603_OV]  13.4 7.73 270 top
R335  10.0K  [RC0402_25]  95.11 5.17 90 top
R336  10.0K  [RC0402_25]  101.77 5.12 90 top
R337  330 OHM  [RC0402_25]  9.94 2.88 0 top
R500  0  [RC0603]  4.91 78.06 270 bottom
R501  0  [RC0603]  103.42 77.94 90 bottom
R502  33K  [RC0402_25]  7.84 77.56 180 bottom
R503  33K  [RC0402_25]  11.65 77.15 180 bottom
R504  10.0K  [RC0402_25]  7.84 76.59 180 bottom
R505  10.0K  [RC0402_25]  11.65 76.19 180 bottom
R506  0  [RC0402_25]  68.08 70.37 90 bottom
R507  0  [RC0402_25]  95.08 69.94 0 bottom
R508  0  [RC0402_25]  69.58 69.86 0 bottom
R509  0  [RC0603]  79.16 69.3 0 bottom
R510  0  [RC0402_25]  95.08 68.41 0 bottom
R511  0  [RC0402_25]  24.19 66.91 270 bottom
R512  0  [RC0402_25]  25.41 66.86 270 bottom
R513  0  [RC0603]  104.48 66.76 180 bottom
R514  0  [RC0603]  104.48 65.36 180 bottom
R515  0  [RC0402_25]  95.08 65.36 0 bottom
R516  0  [RC0402_25]  95.08 63.84 0 bottom
R517  0  [RC0603]  21.55 63.71 90 bottom
R518  10K  [RC0603_OV]  95.39 62.57 180 bottom
R519  0  [RC0402_25]  15.2 61.61 270 bottom
R520  0  [RC0402_25]  16.5 61.43 270 bottom
R521  0  [RC0603]  98.41 61 90 bottom
R522  0  [RC0603]  99.83 60.97 90 bottom
R523  10K  [RC0603_OV]  34.02 60.18 180 bottom
R524  0  [RC0402_25]  75.65 58.76 180 bottom
R525  10.0K  [RC0402_25]  22.06 58.33 90 bottom
R526  0  [RC0603]  18.45 58.18 270 bottom
R527  0  [RC0603]  19.82 58.15 270 bottom
R528  0  [RC0402_25]  29.93 57.87 180 bottom
R529  0  [RC0402_25]  75.65 57.74 180 bottom
R530  0  [RC0402_25]  12.33 57.21 180 bottom
R531  10.0K  [RC0402_25]  27.32 56.93 270 bottom
R532  0  [RC0402_25]  26.33 56.93 270 bottom
R533  0  [RC0402_25]  75.65 56.73 180 bottom
R534  0  [RC0402_25]  28.94 56.32 90 bottom
R535  0  [RC0402_25]  12.33 56.27 180 bottom
R536  0  [RC0402_25]  18.05 56.09 0 bottom
R537  0  [RC0402_25]  34.96 55.92 180 bottom
R538  0  [RC0402_25]  75.65 55.71 180 bottom
R539  10K  [RC0603_OV]  100.98 55.51 270 bottom
R540  0  [RC0402_25]  19.75 54.87 0 bottom
R541  0  [RC0402_25]  75.65 54.7 180 bottom
R542  0  [RC0402_25]  16.37 54.57 270 bottom
R543  0  [RC0402_25]  15.41 54.57 270 bottom
R544  0  [RC0402_25]  75.65 53.68 180 bottom
R545  10K  [RC0603_OV]  96.69 53.53 0 bottom
R546  51K  [RC0402_25]  38.19 52.92 270 bottom
R547  51K  [RC0402_25]  37.17 52.92 270 bottom
R548  51K  [RC0402_25]  36.16 52.92 270 bottom
R549  0  [RC0402_25]  96.94 52.26 0 bottom
R550  0  [RC0603]  24.83 51.55 0 bottom
R551  10K  [RC0603_OV]  103.09 51.22 180 bottom
R552  0  [RC0402_25]  41.41 51.12 270 bottom
R553  0  [RC0402_25]  42.91 50.71 0 bottom
R554  0  [RC0402_25]  36.23 50.63 180 bottom
R555  0  [RC0402_25]  34.23 50.02 180 bottom
R556  10K  [RC0603_OV]  100.52 49.08 180 bottom
R557  51K  [RC0402_25]  45.4 49.01 270 bottom
R558  51K  [RC0402_25]  44.39 49.01 270 bottom
R559  51K  [RC0402_25]  43.37 49.01 270 bottom
R560  51K  [RC0402_25]  42.35 49.01 270 bottom
R561  0  [RC0402_25]  61.56 48.96 180 bottom
R562  0  [RC0402_25]  61.56 47.99 180 bottom
R563  0  [RC0402_25]  27.52 47.18 90 bottom
R564  0  [RC0402_25]  26.5 47.15 90 bottom
R565  0  [RC0402_25]  61.56 47.03 180 bottom
R566  51K  [RC0402_25]  38.47 47.03 180 bottom
R567  0  [RC0402_25]  61.56 46.06 180 bottom
R568  51K  [RC0402_25]  40.35 44.79 90 bottom
R569  51K  [RC0402_25]  38.19 44.79 90 bottom
R570  51K  [RC0402_25]  40.35 42.63 270 bottom
R571  51K  [RC0402_25]  39.33 42.63 270 bottom
R572  51K  [RC0402_25]  38.32 42.63 270 bottom
R573  51K  [RC0402_25]  42.15 40.88 180 bottom
R574  0  [RC0402_25]  38.95 40.73 0 bottom
R575  10.0K  [RC0603]  36.33 40.73 180 bottom
R576  51K  [RC0402_25]  46.65 40.37 90 bottom
R577  51K  [RC0402_25]  45.63 40.37 90 bottom
R578  51K  [RC0402_25]  44.62 40.37 90 bottom
R579  51K  [RC0402_25]  43.6 40.37 90 bottom
R580  0  [RC0402_25]  40.4 40.24 90 bottom
R581  33 OHM  [RC0402_25]  36.28 38.82 180 bottom
R582  51K  [RC0402_25]  47.59 38.69 0 bottom
R583  0  [RC0402_25]  62.8 38.34 180 bottom
R584  51K  [RC0402_25]  47.59 37.68 0 bottom
R585  33 OHM  [RC0402_25]  36.28 37.55 180 bottom
R586  33 OHM  [RC0402_25]  23.96 37.55 0 bottom
R587  51K  [RC0402_25]  56.1 36.69 180 bottom
R588  51K  [RC0402_25]  47.59 36.66 0 bottom
R589  51K  [RC0402_25]  61.99 36.38 180 bottom
R590  33 OHM  [RC0402_25]  36.28 36.28 180 bottom
R591  33 OHM  [RC0402_25]  23.96 36.28 0 bottom
R592  51K  [RC0402_25]  56.1 35.65 180 bottom
R593  51K  [RC0402_25]  47.59 35.65 0 bottom
R594  51K  [RC0402_25]  61.99 35.42 180 bottom
R595  33 OHM  [RC0402_25]  23.96 35.01 0 bottom
R596  51K  [RC0402_25]  56.1 34.63 180 bottom
R597  51K  [RC0402_25]  61.99 34.48 180 bottom
R598  51K  [RC0402_25]  53.51 34.12 90 bottom
R599  51K  [RC0402_25]  43.24 33.82 90 bottom
R600  51K  [RC0402_25]  41.21 33.82 90 bottom
R601  51K  [RC0402_25]  40.2 33.82 90 bottom
R602  51K  [RC0402_25]  39.18 33.82 90 bottom
R603  51K  [RC0402_25]  61.99 33.54 180 bottom
R604  0  [RC0402_25]  59.14 33.39 0 bottom
R605  10.0K  [RC0402_25]  21.22 28.61 180 bottom
R606  10.0K  [RC0402_25]  24.09 25.87 270 bottom
R607  10.0K  [RC0402_25]  14.26 25.82 270 bottom
R608  10.0K  [RC0402_25]  23.81 23.78 180 bottom
R609  0  [RC0402_25]  20.18 21.47 270 bottom
R610  4.7K  [RC0402_25]  34.63 20.46 0 bottom
R611  10.0K  [RC0402_25]  37.55 19.57 180 bottom
R612  10.0K  [RC0402_25]  23.96 18.68 0 bottom
R613  10.0K  [RC0402_25]  32.73 18.55 0 bottom
R614  180K  [RC0402_25]  37.05 18.04 90 bottom
R615  4.7K  [RC0402_25]  23.96 17.66 180 bottom
R616  10.0K  [RC0402_25]  33.11 16.9 90 bottom
R617  33  [RC0402_25]  12.53 16.65 0 bottom
R618  33  [RC0402_25]  12.53 15.63 0 bottom
R619  0  [RC0402_25]  23.89 15.5 90 bottom
R620  0  [RC0402_25]  22.95 15.5 90 bottom
R621  4.7K  [RC0402_25]  25.11 15.12 270 bottom
R622  4.7K  [RC0402_25]  29.81 14.23 270 bottom
R623  10.0K  [RC0402_25]  32.6 12.71 0 bottom
R624  0  [RC0402_25]  30.31 12.71 0 bottom
R625  0  [RC0402_25]  28.16 12.58 180 bottom
R626  10.0K  [RC0402_25]  26.28 12.15 180 bottom
R627  0  [RC0402_25]  19.9 11.87 0 bottom
R628  4.7K  [RC0402_25]  15.51 11.39 90 bottom
R629  10.0K  [RC0402_25]  14.54 11.39 270 bottom
R630  10.0K  [RC0402_25]  18.81 9.74 270 bottom
R631  4.7K  [RC0402_25]  17.87 9.74 90 bottom
R632  0  [RC0603]  20.15 63.71 90 bottom
R633  0  [RC0603]  51.85 54.19 0 top
R634  0  [RC0402_25]  70.27 46.04 270 bottom
R635  0  [RC0402_25]  70.93 38.24 180 bottom
SW1  Electrode  [ELECTRODE_SQ_15MM]  115.4 31.33 90 top
SW2  Electrode  [ELECTRODE_SQ_15MM]  115.4 13.17 90 top
SW3  EVQ-P2402W  [SW4_SPST_4P8X3P6_2P5]  91.4 7.2 90 top
SW4  EVQ-P2402W  [SW4_SPST_4P8X3P6_2P5]  98.01 7.2 90 top
SW5  EVQ-P2402W  [SW4_SPST_4P8X3P6_2P5]  10.22 7.05 270 top
SW6  EVQ-P2402W  [SW4_SPST_4P8X3P6_2P5]  16.6 7 270 top
TP1  -  [TPAD_028]  34.58 74.94 0 top
TP2  -  [TPAD_028]  32.37 74.28 0 top
TP3  -  [TPAD_028]  95.72 72.6 0 top
TP4  -  [TPAD_028]  22.44 71.97 0 top
TP5  TEST_POINT  [TP_TH_063]  14.59 71.89 0 top
TP6  -  [TPAD_028]  97.88 70.06 0 top
TP7  -  [TPAD_028]  14.74 66.46 0 top
TP8  TEST_POINT  [TP_TH_063]  14.69 63.97 0 top
TP9  -  [TPAD_028]  33.11 63.84 270 top
TP10  -  [TPAD_028]  22.44 61.94 90 top
TP11  -  [TPAD_028]  16.13 61.86 270 top
TP12  -  [TPAD_028]  23.58 61.81 0 top
TP13  -  [TPAD_028]  20.13 61.71 0 top
TP14  -  [TPAD_028]  21.25 61.68 90 top
TP15  -  [TPAD_028]  24.73 61.68 0 top
TP16  -  [TPAD_028]  31.99 60.51 270 top
TP17  -  [TPAD_028]  29.04 56.86 270 top
TP20  -  [TPAD_028]  10.25 56.47 270 top
TP21  -  [TPAD_028]  31.56 56.12 180 top
TP22  -  [TPAD_028]  30.92 53.4 0 top
TP24  -  [TPAD_028]  12.92 53.55 0 top
TP25  -  [TPAD_028]  30.98 54.52 0 top
TP26  TEST_POINT  [TP_TH_063]  51.14 51.39 0 top
TP27  -  [TPAD_028]  112.61 50.89 0 top
TP28  -  [TPAD_028]  12.94 46.7 225 top
TP29  -  [TPAD_028]  10.76 44.66 90 top
TP30  -  [TPAD_028]  16.34 44.54 270 top
TP34  -  [TPAD_028]  17.95 44.41 0 top
TP37  -  [TPAD_028]  19.11 44.41 45 top
TP38  -  [TPAD_028]  20.31 44.38 0 top
TP39  -  [TPAD_028]  22.01 44.33 270 top
TP40  -  [TPAD_028]  24.93 43.93 0 top
TP41  -  [TPAD_028]  23.58 43.14 0 top
TP42  -  [TPAD_028]  89.7 42.81 0 top
TP43  -  [TPAD_028]  93.97 40.98 0 top
TP44  -  [TPAD_028]  91.15 39.71 0 top
TP45  -  [TPAD_028]  8.85 39.33 315 top
TP46  -  [TPAD_028]  93.94 38.31 0 top
TP47  -  [TPAD_028]  24.6 36.92 90 top
TP48  -  [TPAD_028]  93.99 36.15 0 top
TP49  -  [TPAD_028]  91.15 34.5 0 top
TP50  -  [TPAD_028]  35.52 33.67 0 top
TP51  -  [TPAD_028]  7.45 33.11 0 top
TP52  -  [TPAD_028]  38.06 31.46 0 top
TP53  -  [TPAD_028]  35.52 31.38 0 top
TP54  -  [TPAD_028]  9.61 29.04 0 top
TP55  -  [TPAD_030]  33.74 21.19 0 top
TP56  -  [TPAD_028]  90.13 18.93 0 top
TP57  -  [TPAD_030]  22.67 17.51 180 top
TP58  -  [TPAD_028]  48.27 16.57 0 top
TP59  -  [TPAD_028]  90.26 15.45 0 top
TP60  -  [TPAD_028]  95.08 3.64 90 top
TP61  -  [TPAD_028]  100.8 3.52 90 top
TP500  -  [TPAD_028]  22.82 62.7 0 bottom
TP501  -  [TPAD_028]  27.57 61.48 180 bottom
TP502  -  [TPAD_028]  28.79 61.43 180 bottom
TP503  -  [TPAD_028]  31.23 59.62 180 bottom
TP504  -  [TPAD_028]  16.04 57.06 180 bottom
TP505  -  [TPAD_028]  26.61 52.72 90 bottom
TP506  -  [TPAD_028]  63.16 47.97 180 bottom
TP507  -  [TPAD_028]  63.16 46.75 180 bottom
TP508  -  [TPAD_030]  15.58 20.97 270 bottom
TP509  -  [TPAD_030]  14.31 20.97 0 bottom
TP510  -  [TPAD_030]  21.93 17.92 180 bottom
TP511  -  [TPAD_030]  21.55 15 180 bottom
TP512  -  [TPAD_030]  7.84 14.62 0 bottom
TPAD1  -  [TPAD_030]  120.1 79.46 0 top
TPAD2  -  [TPAD_030]  123.28 76.79 0 top
TPAD3  -  [TPAD_030]  103.21 76.67 0 top
TPAD4  -  [TPAD_030]  118.71 76.03 0 top
TPAD5  -  [TPAD_030]  103.21 75.4 0 top
TPAD6  -  [TPAD_030]  28.28 74.76 0 top
TPAD7  -  [TPAD_030]  40.02 74.61 0 top
TPAD8  -  [TPAD_030]  30.8 74.31 0 top
TPAD9  -  [TPAD_030]  76.52 74.05 0 top
TPAD10  -  [TPAD_030]  122.16 71.21 0 top
TPAD11  -  [TPAD_030]  119.14 70.55 0 top
TPAD12  -  [TPAD_030]  59.47 69.76 0 top
TPAD13  -  [TPAD_030]  121.63 69.56 0 top
TPAD14  -  [TPAD_030]  76.8 69.3 0 top
TPAD15  -  [TPAD_030]  48.45 68.64 0 top
TPAD16  -  [TPAD_030]  122.54 68.62 0 top
TPAD17  -  [TPAD_030]  84.54 67.52 0 top
TPAD18  -  [TPAD_030]  122.54 67.45 0 top
TPAD19  -  [TPAD_030]  122.54 66.28 0 top
TPAD20  -  [TPAD_030]  51.14 66.13 0 top
TPAD21  -  [TPAD_030]  106.64 65.36 0 top
TPAD22  -  [TPAD_030]  122.54 65.06 0 top
TPAD23  -  [TPAD_030]  52.41 64.86 0 top
TPAD24  -  [TPAD_030]  84.47 63.84 0 top
TPAD25  -  [TPAD_030]  119.72 62.7 0 top
TPAD26  -  [TPAD_030]  84.47 62.57 0 top
TPAD28  -  [TPAD_030]  121.42 58.3 0 top
TPAD29  -  [TPAD_030]  25.23 58.48 0 top
TPAD30  -  [TPAD_030]  29.12 58.02 0 top
TPAD31  -  [TPAD_030]  104.25 57.36 0 top
TPAD32  -  [TPAD_030]  51.9 57.24 0 top
TPAD33  -  [TPAD_030]  99.91 55.84 0 top
TPAD34  -  [TPAD_030]  104.36 55.84 0 top
TPAD35  -  [TPAD_030]  52.67 55.41 0 top
TPAD36  -  [TPAD_030]  94.96 54.19 0 top
TPAD37  -  [TPAD_030]  100.8 49.36 0 top
TPAD38  -  [TPAD_030]  88.43 42.78 0 top
TPAD39  -  [TPAD_030]  31.97 42.63 0 top
TPAD40  -  [TPAD_030]  48.98 41.87 0 top
TPAD41  -  [TPAD_030]  86.19 39.74 0 top
TPAD42  -  [TPAD_030]  61.18 38.31 0 top
TPAD43  -  [TPAD_030]  85.69 37.53 0 top
TPAD44  -  [TPAD_030]  77.89 37.15 0 top
TPAD45  -  [TPAD_030]  54.32 33.61 0 top
TPAD46  -  [TPAD_030]  99.78 32.34 270 top
TPAD47  -  [TPAD_030]  106.13 32.22 270 top
TPAD48  -  [TPAD_030]  35.14 21.45 0 top
TPAD49  -  [TPAD_030]  12.89 17.51 0 top
TPAD50  -  [TPAD_030]  83.22 15.17 270 top
TPAD51  -  [TPAD_030]  22.54 13.17 270 top
TPAD52  -  [TPAD_030]  100.93 12.41 270 top
TPAD53  -  [TPAD_030]  106.49 12.41 270 top
TPAD54  -  [TPAD_030]  12.1 2.91 0 top
TPAD500  -  [TPAD_030]  12.15 78.24 180 bottom
TPAD501  -  [TPAD_030]  9.39 76.59 180 bottom
TPAD502  -  [TPAD_030]  11.14 75.17 180 bottom
TPAD503  -  [TPAD_030]  98.62 49.08 180 bottom
TPAD504  -  [TPAD_030]  37.12 42 180 bottom
TPAD505  -  [TPAD_030]  51.83 61.05 0 top
TS1  TESTLOOP  [TESTPOINT_135_070MIL]  73.11 74.03 0 top
TS2  TESTLOOP  [TESTPOINT_135_070MIL]  26.89 72.93 180 top
TS3  TESTLOOP  [TESTPOINT_135_070MIL]  79.44 72.71 0 top
TS4  TESTLOOP  [TESTPOINT_135_070MIL]  89.5 71.59 180 top
TS5  TESTLOOP  [TESTPOINT_135_070MIL]  21.81 69.33 90 top
TS6  TESTLOOP  [TESTPOINT_135_070MIL]  99.68 63.54 90 top
TS7  TESTLOOP  [TESTPOINT_135_070MIL]  115.81 56.83 180 top
TS8  TESTLOOP  [TESTPOINT_135_070MIL]  42 52.54 90 top
TS9  TESTLOOP  [TESTPOINT_135_070MIL]  115.4 51.27 180 top
TS10  TESTLOOP  [TESTPOINT_135_070MIL]  30.19 50.12 90 top
TS11  TESTLOOP  [TESTPOINT_135_070MIL]  30.16 44.03 90 top
TS12  TESTLOOP  [TESTPOINT_135_070MIL]  104.41 38.42 90 top
TS13  TESTLOOP  [TESTPOINT_135_070MIL]  29.17 34.1 0 top
TS14  TESTLOOP  [TESTPOINT_135_070MIL]  71.84 33.74 90 top
TS15  TESTLOOP  [TESTPOINT_135_070MIL]  40.22 16.7 270 top
TS16  TESTLOOP  [TESTPOINT_135_070MIL]  88.2 12.38 270 top
U1  AP1509-SG-13  [SO8_1P27_4X5]  51.78 70.7 90 top
U3  NTSX2102GU8H  [XQFN8_1P45X1P25MM]  101.18 53.81 0 top
U7  PS32K118UEX0MLQT  [LQFP144_0P5_20X20MM]  68.54 53.68 270 top
U8  PS32K118UEX0MLUT  [TQFP176]  68.54 53.68 270 top
U9  UJA1131HW/FD/5V/0  [HTQFP48_0P65_10X10_EP_5MM]  20.66 51.78 180 top
U10  NTSX2102GU8H  [XQFN8_1P45X1P25MM]  93.69 50.12 270 top
U11  TXB0104  [QFN14_RGY]  38.57 48.73 0 top
U12  NTSX2102GU8H  [XQFN8_1P45X1P25MM]  100.93 45.93 0 top
U13  TXB0104  [QFN14_RGY]  45.05 44.54 180 top
U14  TXB0104  [QFN14_RGY]  39.84 38.57 0 top
U16  TXB0104  [QFN14_RGY]  51.78 36.41 90 top
U22  TXB0104  [QFN14_RGY]  63.33 35.52 90 top
U23  74LVC2G14GV  [SC74_6P_1P7X3P1]  19.8 21.32 270 top
U24  MIC2005-0.8YM6  [SOT23-6_A]  11.65 15.12 0 top
U500  NTSX2102GU8H  [XQFN8_1P45X1P25MM]  24.85 63.97 0 bottom
U501  NTSX2102GU8H  [XQFN8_1P45X1P25MM]  28.79 59.65 180 bottom
U502  NTSX2102GU8H  [XQFN8_1P45X1P25MM]  16.04 58.86 0 bottom
U503  NTSX2102GU8H  [XQFN8_1P45X1P25MM]  34 57.77 180 bottom
U504  NTSX2102GU8H  [XQFN8_1P45X1P25MM]  22.14 55.92 90 bottom
U505  NTSX2102GU8H  [XQFN8_1P45X1P25MM]  99.78 52.36 0 bottom
U506  NTSX2102GU8H  [XQFN8_1P45X1P25MM]  33.69 52.13 180 bottom
U507  NTSX2102GU8H  [XQFN8_1P45X1P25MM]  26.96 49.46 180 bottom
U508  MX25L6433FM2R-08G  [SO8_W]  30.19 36.92 180 bottom
U509  NTSX2102GU8H  [XQFN8_1P45X1P25MM]  35.14 18.55 90 bottom
U510  MK20DX128VFM5  [QFN32_S142EP]  17.49 16.9 0 bottom
U511  74LVCH1T45  [UDFN6_1X1P5MM]  31.71 14.23 270 bottom
U512  74LVCH1T45  [UDFN6_1X1P5MM]  27.14 14.11 270 bottom
U513  74LVC2T45GM,125  [QFN8_1P6X1P6MM]  22.44 13.22 180 bottom
U514  74LVCH1T45  [UDFN6_1X1P5MM]  17.89 11.82 270 bottom
U515  RClamp0502A.TCT  [SOT666]  9.11 11.57 180 bottom
Y1  8MHZ  [XTAL2_3P3X2P6]  67.53 72.6 180 top
Y500  50MHZ  [XTLOSC4_SM]  102.58 71.84 270 bottom
Y501  8.00MHZ  [XTAL3_3P35X1P45_SM]  22.57 21.09 270 bottom

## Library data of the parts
C1-C4 C6 C7 C9 C10 C12-C15 C17 C20-C25 C28 C29 C31 C32 C43-C45 C47 C50 C53 C54 C57-C60 C62-C67 C69-C73 C77-C79 C82 C85-C88 C99 C108-C112 C114-C116 C502-C509 C512-C516 C519-C522 C524-C526 C528-C530 C532 C534 C537 C541 C543 C545 C547-C551 = CAP_NP
C5 C18 C19 C26 C27 C30 C41 C46 C48 C49 C55 C56 C61 C68 C75 C80 C81 C83 C84 C89 C97 C104 C113 C500 C501 C510 C511 C517 C518 C523 C527 C531 C533 C535 C536 C538-C540 C542 C544 C546 = CAP_NP: tolerance: 10%
C8 C11 C16 = CAP_POL
C103 = CAP_NP: tolerance: 5%
D1 D2 = TRANZORB_BIDIR_AA
D4 D5 D8 D9 D500 = DIODE_SCHTKY
D6 = LED_TRI_COLOR
D7 D10 D11 DS1-DS3 = LED
GND1-GND5 = TEST_POINT_3
J1 J3 J4 = HDR-3X8_A
J2 J6 = HDR-3X10_A
J5 J10 = CONN_HDR_10X2
J7 J8 J18 J22 = CONN_HDR_3X1
J9 = DC_POWER_JACK_SHD
J11 J13 J17 = CONN_HDR_4X1
J12 J21 = JUMPER_2_2mm
J14 = CONN_HDR_2X2
J15 = CONN_HDR_4X2
J16 = QSH030
J19 J23 = CONN_HDR_2X1
J20 = CONN_HDR_5X2: User Part Number: 210-07961-00
J24 = MICRO_USB_CONN_10PIN
JP1 = CONN_HDR_1X1
L1 L6 L7 L500 = INDUCTOR_FERRITE
L2 L9 L501 = BEAD
L3 = INDUCTOR: tolerance: 30%
L4 = BEAD: tolerance: 25%
L8 = INDUCTOR
P1 = CONN_HDR_25X2
Q1-Q3 Q500 Q501 = NPN
R1-R8 R14 R34-R41 R46 R55 R58-R64 R72 R74-R76 R78-R81 R90-R98 R102 R106-R115 R119 R121-R131 R133-R139 R141 R142 R144 R148-R150 R153 R154 R156 R161 R163 R165 R173 R175-R185 R187-R221 R223-R228 R230-R234 R242-R244 R246 R248-R254 R257-R261 R263-R284 R287-R292 R294 R298 R299 R302 R304 R306-R334 R337 R500-R503 R506-R524 R526-R530 R532-R574 R576-R609 R612 R614 R617 R618 R624 R625 R629 R632-R635 = RES
R9 R12 R13 R229 R247 R256 R262 R285 R286 R295 R305 R611 R613 R616 R619 R620 R623 R626 R627 R630 = RES: tolerance: 5%
R132 R140 R222 R245 R255 R293 R296 R300 R301 R335 R336 R504 R505 R525 R531 R575 R610 R615 R621 R622 R628 R631 = RES: tolerance: 1%
R186 = POT: tolerance: 20%
SW1 SW2 = ELECTRODE
SW3-SW6 = EDGE_MOUNT_PB_SW_2
TP1-TP4 TP6 TP7 TP9-TP17 TP20-TP22 TP24 TP25 TP27-TP30 TP34 TP37-TP54 TP56 TP58-TP61 TP500-TP507 = TESTLOOP
TP5 TP8 TP26 = TEST_POINT_0
TP55 TP57 TP508-TP512 TPAD1-TPAD26 TPAD28-TPAD54 TPAD500-TPAD505 = TestLoop
TS1-TS16 = TEST_POINT_4
U1 = AP1509_ADJ
U3 U10 U12 U500-U507 U509 = NTSX2102GU8H_8P
U7 = S32K1XX_LQFP_144P
U8 = S32K1XX_LQFP_176P
U9 = UJA1132HW_FD_HTQFP_48P_EP_7
U11 U13 U14 U16 U22 = TXB0104
U23 = NC7WP14
U24 = MIC2005-0.8YM6
U508 = MX25L6433FM2R_SOP8
U510 = PK20DX128V_QFN_32P
U511 U512 U514 = 74LVCH1T45_6P
U513 = 74LVC2T45GM_8P
U515 = RClamp0502A_6P
Y1 = XTAL_CS10
Y500 = CLKGEN-SM
Y501 = XTAL_CS

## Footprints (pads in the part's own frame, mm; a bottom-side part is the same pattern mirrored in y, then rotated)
0805
  rect 1.27x1.27 smd: 1(-0.889,0) 2(0.889,0)
CC0402_25
  round 0.635 smd: 1(-0.508,0) 2(0.508,0)
CC0603
  rect 0.991x0.813 smd: 1(-0.686,0) 2(0.686,0)
CC0603_OV
  oval 0.889x1.143 smd: 1(-0.762,0) 2(0.762,0)
CC0805_OV
  oval 0.889x1.524 smd: 1(-0.965,0) 2(0.965,0)
CC1210
  rect 1.778x2.845 smd: 1(-1.397,0) 2(1.397,0)
CCE6P8X6P8
  rect 3.556x1.651 smd: 1(-2.35,0) 2(2.35,0)
CON3_PWR_JACK_TH_PJ051A
  round 0.254 hole 2.54 unplated: (-6.3,3.3)
  oval 3.454x1.448 hole 2.819x0.813: 1(0,0) 2(0,8.6) 3(0,3.4)
  oval 3.734x1.448 hole 3.099x0.813: SH1(-7.3,9.5) SH2(-7.3,-0.4)
CON_2RH_10_50
  oval 1.067x1.676 hole 0.787: 1(0,0) 2(0,1.27) 3(1.27,0) 4(1.27,1.27) 5(2.54,0) 6(2.54,1.27) 7(3.81,0) 8(3.81,1.27) 9(5.08,0) 10(5.08,1.27)
CON_3X8_100_TH
  rect 1.651x1.651 hole 1.016: 1(0,0)
  round 1.651 hole 1.016: 2(0,-2.54) 3(0,-5.08) 4(2.54,0) 5(2.54,-2.54) 6(2.54,-5.08) 7(5.08,0) 8(5.08,-2.54) 9(5.08,-5.08) 10(7.62,0) 11(7.62,-2.54) 12(7.62,-5.08) 13(10.16,0) 14(10.16,-2.54) 15(10.16,-5.08) 16(12.7,0) 17(12.7,-2.54) 18(12.7,-5.08) 19(15.24,0) 20(15.24,-2.54) 21(15.24,-5.08) 22(17.78,0) 23(17.78,-2.54) 24(17.78,-5.08)
CON_3X10_100_TH
  rect 1.651x1.651 hole 1.016: 1(0,0)
  round 1.651 hole 1.016: 2(0,-2.54) 3(0,-5.08) 4(2.54,0) 5(2.54,-2.54) 6(2.54,-5.08) 7(5.08,0) 8(5.08,-2.54) 9(5.08,-5.08) 10(7.62,0) 11(7.62,-2.54) 12(7.62,-5.08) 13(10.16,0) 14(10.16,-2.54) 15(10.16,-5.08) 16(12.7,0) 17(12.7,-2.54) 18(12.7,-5.08) 19(15.24,0) 20(15.24,-2.54) 21(15.24,-5.08) 22(17.78,0) 23(17.78,-2.54) 24(17.78,-5.08) 25(20.32,0) 26(20.32,-2.54) 27(20.32,-5.08) 28(22.86,0) 29(22.86,-2.54) 30(22.86,-5.08)
CON_60S_QSH_SM_A
  round 0.254 hole 1.016 unplated: (-10.067,2.667) (10.067,2.667)
  rect 0.279x2.286 smd: 1(-7.256,-2.865) 2(-7.256,2.865) 3(-6.755,-2.865) 4(-6.755,2.865) 5(-6.255,-2.865) 6(-6.255,2.865) 7(-5.754,-2.865) 8(-5.754,2.865) 9(-5.254,-2.865) 10(-5.254,2.865) 11(-4.754,-2.865) 12(-4.754,2.865) 13(-4.253,-2.865) 14(-4.253,2.865) 15(-3.753,-2.865) 16(-3.753,2.865) 17(-3.252,-2.865) 18(-3.252,2.865) 19(-2.752,-2.865) 20(-2.752,2.865) 21(-2.252,-2.865) 22(-2.252,2.865) 23(-1.751,-2.865) 24(-1.751,2.865) 25(-1.251,-2.865) 26(-1.251,2.865) 27(-0.751,-2.865) 28(-0.751,2.865) 29(-0.25,-2.865) 30(-0.25,2.865) 31(0.25,-2.865) 32(0.25,2.865) 33(0.751,-2.865) 34(0.751,2.865) 35(1.251,-2.865) 36(1.251,2.865) 37(1.751,-2.865) 38(1.751,2.865) 39(2.252,-2.865) 40(2.252,2.865) 41(2.752,-2.865) 42(2.752,2.865) 43(3.252,-2.865) 44(3.252,2.865) 45(3.753,-2.865) 46(3.753,2.865) 47(4.253,-2.865) 48(4.253,2.865) 49(4.754,-2.865) 50(4.754,2.865) 51(5.254,-2.865) 52(5.254,2.865) 53(5.754,-2.865) 54(5.754,2.865) 55(6.255,-2.865) 56(6.255,2.865) 57(6.755,-2.865) 58(6.755,2.865) 59(7.256,-2.865) 60(7.256,2.865)
  rect 2.54x0.432 smd: SH1(-8.065,0) SH4(8.065,0)
  rect 4.699x0.432 smd: SH2(-3.175,0) SH3(3.175,0)
CON_HDR_4M_100_TH_RA
  rect 1.651x1.651 hole 1.016: 1(0,0)
  round 1.651 hole 1.016: 2(2.54,0) 3(5.08,0) 4(7.62,0)
CON_MICROAB_10F_25_SM_RA
  rect 1.372x0.406 smd: 1(2.575,-1.3) 2(2.575,-0.65) 3(2.575,0) 4(2.575,0.65) 5(2.575,1.3)
  oval 1.27x1.067 hole 0.864x0.66: 6(2.9,2.225) 7(2.9,-2.225)
  rect 1.905x2.921 smd: 8(-0.1,0)
  custom 0.356x0.356 hole 1.524x0.838: 9(-0.1,4.09) 10(-0.1,-4.09)
